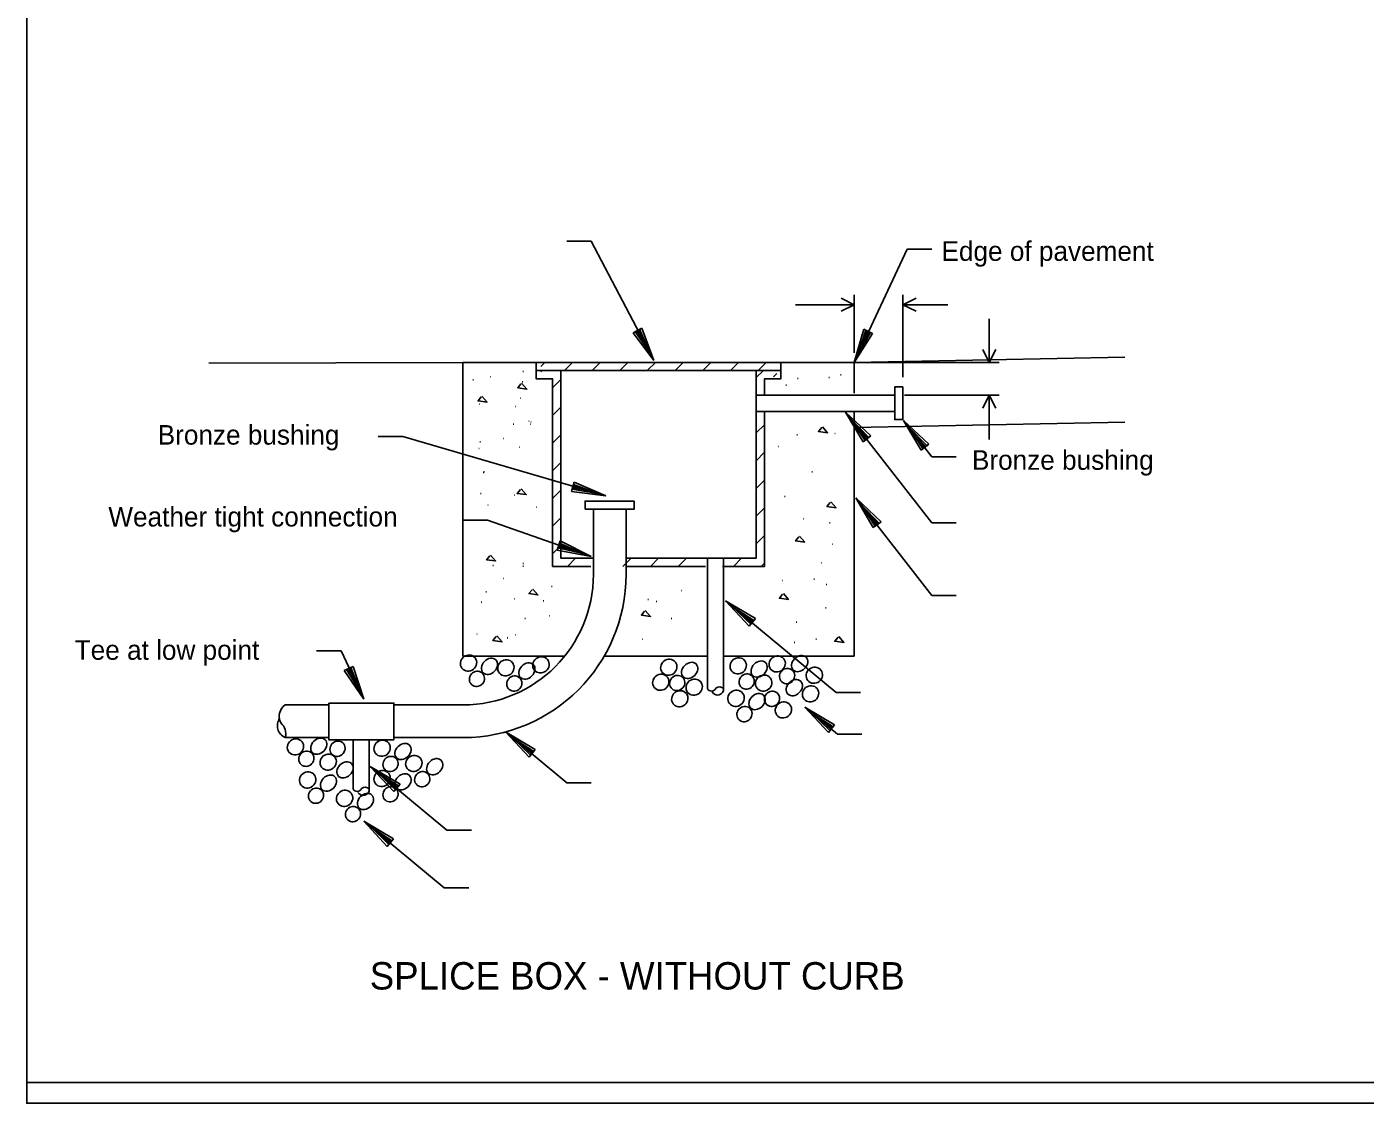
# Model space of a CAD drawing. Extents: x 0 to 390, y 0 to 265.
# Drawn here: x 0 to 160.8, y 0 to 129.2 of the extents above; entities that cross this region are included whole.
import ezdxf

# ---------------------------------------------------------------- set-up
doc = ezdxf.new("R2010")
doc.units = 0
doc.layers.add('D_Details', color=7, linetype='Continuous')
doc.layers.add('Default', color=7, linetype='Continuous')

msp = doc.modelspace()

# ---------------------------------------------------------------- linework, layer by layer
at = {"layer": 'D_Details'}
for p, q in [((67.82, 103.5), (64.88, 103.5)), ((67.82, 103.5), (75.32, 89.17)), ((105.78, 102.53), (99.39, 88.93)), ((105.78, 102.53), (108.72, 102.53)), ((99.39, 90.1), (99.39, 97.05)), ((105.26, 87.17), (105.26, 97.05)), ((99.39, 95.87), (92.34, 95.87)), ((105.26, 95.87), (110.64, 95.87)), ((115.62, 88.93), (115.62, 94.19)), ((73.88, 93.06), (72.84, 92.51)), ((72.84, 92.51), (75.32, 89.17)), ((74.85, 90.08), (73.1, 92.65)), ((74.07, 91.5), (73.23, 92.72)), ((73.5, 92.85), (74.07, 91.5)), ((73.63, 92.92), (74.85, 90.08)), ((75.32, 89.17), (73.88, 93.06)), ((100.55, 92.92), (99.39, 88.93)), ((99.39, 88.93), (101.61, 92.42)), ((99.82, 89.86), (100.82, 92.8)), ((101.35, 92.55), (99.82, 89.86)), ((100.48, 91.33), (100.95, 92.74)), ((101.22, 92.61), (100.48, 91.33)), ((101.61, 92.42), (100.55, 92.92)), ((52.4, 88.93), (21.87, 88.86)), ((52.4, 53.69), (52.4, 88.93)), ((52.4, 88.93), (59.8, 88.93)), ((59.8, 88.93), (99.39, 88.93)), ((61.19, 86.98), (61.19, 88.93)), ((61.75, 88.93), (61.19, 88.93)), ((61.75, 88.44), (62.24, 88.93)), ((61.75, 88.93), (89.47, 88.93)), ((89.47, 88.93), (61.75, 88.93)), ((89.47, 88.93), (91.63, 88.93)), ((99.39, 88.93), (131.92, 89.58)), ((99.39, 85.24), (99.39, 88.93)), ((99.39, 88.93), (102.32, 88.93)), ((100.56, 88.93), (116.8, 88.93)), ((53.59, 86.83), (53.65, 86.83)), ((55.7, 87.22), (55.75, 87.22)), ((59.61, 87.85), (59.67, 87.85)), ((61.75, 87.8), (61.92, 87.97)), ((61.75, 87.97), (89.47, 87.97)), ((87.64, 84.98), (87.64, 87.97)), ((88.63, 84.98), (88.63, 86.98)), ((89.47, 86.98), (88.63, 86.98)), ((90.6, 86.98), (89.47, 86.98)), ((89.71, 87.19), (90.11, 87.59)), ((90.6, 86.98), (90.6, 87.97)), ((92.61, 86.99), (92.67, 86.99)), ((96.36, 87.14), (96.42, 87.14)), ((97.77, 87.46), (97.83, 87.46)), ((59.53, 86.6), (59.59, 86.6)), ((91.2, 86.2), (91.26, 86.2)), ((54.37, 83.94), (54.43, 83.94)), ((58.67, 83.63), (58.73, 83.63)), ((59.3, 84.64), (59.35, 84.64)), ((87.64, 85.01), (104.27, 85.01)), ((87.64, 85.01), (87.64, 83.06)), ((105.45, 85.01), (116.8, 85.01)), ((115.62, 79.67), (115.62, 85.1)), ((87.64, 83.06), (104.27, 83.06)), ((87.64, 65.44), (87.64, 82.82)), ((88.63, 64.45), (88.63, 82.99)), ((108.72, 69.68), (98.37, 82.96)), ((98.37, 82.96), (100.48, 79.4)), ((101.41, 80.11), (98.37, 82.96)), ((98.37, 82.96), (100.48, 79.4)), ((101.41, 80.11), (98.37, 82.96)), ((100.71, 79.57), (99, 82.15)), ((99, 82.15), (101.18, 79.94)), ((100.71, 79.57), (99, 82.15)), ((99, 82.15), (101.18, 79.94)), ((99.39, 53.69), (99.39, 83.06)), ((58.44, 81.51), (58.5, 81.51)), ((60.31, 81.9), (60.37, 81.9)), ((60.47, 81.51), (60.53, 81.51)), ((60.55, 81.75), (60.61, 81.75)), ((97.07, 80.41), (97.12, 80.41)), ((99.39, 81.11), (131.92, 81.76)), ((100.82, 79.67), (100.02, 80.89)), ((100.02, 80.89), (101.06, 79.84)), ((100.82, 79.67), (100.02, 80.89)), ((100.02, 80.89), (101.06, 79.84)), ((108.72, 77.62), (105.32, 81.98)), ((105.32, 81.98), (107.43, 78.42)), ((108.35, 79.13), (105.32, 81.98)), ((107.66, 78.59), (105.95, 81.17)), ((105.95, 81.17), (108.12, 78.96)), ((42.23, 80.04), (45.16, 80.04)), ((45.16, 80.04), (69.57, 72.92)), ((54.44, 79.4), (54.5, 79.4)), ((57.26, 79.79), (57.32, 79.79)), ((90.26, 78.85), (90.32, 78.85)), ((92.53, 80.26), (92.58, 80.26)), ((100.48, 79.4), (101.41, 80.11)), ((100.48, 79.4), (101.41, 80.11)), ((107.77, 78.69), (106.97, 79.91)), ((106.97, 79.91), (108.01, 78.86)), ((107.43, 78.42), (108.35, 79.13)), ((54.29, 78.62), (54.34, 78.62)), ((59.14, 78.77), (59.2, 78.77)), ((108.72, 77.62), (111.65, 77.62)), ((54.84, 75.73), (54.9, 75.73)), ((54.91, 75.81), (54.97, 75.81)), ((94.33, 75.81), (94.39, 75.81)), ((65.77, 74.58), (65.44, 73.45)), ((65.64, 74.16), (67.02, 73.63)), ((65.69, 74.3), (68.58, 73.21)), ((69.57, 72.92), (65.77, 74.58)), ((54.52, 73.22), (54.58, 73.22)), ((58.59, 72.99), (58.65, 72.99)), ((65.44, 73.45), (69.57, 72.92)), ((68.58, 73.21), (65.52, 73.74)), ((67.02, 73.63), (65.56, 73.88)), ((91.04, 72.83), (91.1, 72.83)), ((108.72, 60.96), (99.59, 72.67)), ((99.59, 72.67), (101.7, 69.11)), ((102.63, 69.82), (99.59, 72.67)), ((55.38, 71.82), (55.44, 71.82)), ((61.18, 71.58), (61.23, 71.58)), ((68.07, 71.31), (71.99, 71.31)), ((68.07, 71.31), (68.07, 63.49)), ((71.99, 71.31), (71.99, 63.46)), ((101.93, 69.28), (100.23, 71.86)), ((100.23, 71.86), (102.4, 69.65)), ((52.42, 70.01), (55.35, 70.01)), ((55.35, 70.01), (67.79, 65.64)), ((93.31, 70.17), (93.37, 70.17)), ((96.44, 69.7), (96.5, 69.7)), ((102.05, 69.38), (101.24, 70.61)), ((101.24, 70.61), (102.28, 69.55)), ((101.7, 69.11), (102.63, 69.82)), ((108.72, 69.68), (111.65, 69.68)), ((64.09, 67.5), (63.7, 66.39)), ((63.7, 66.39), (67.79, 65.64)), ((66.82, 65.98), (63.8, 66.67)), ((65.29, 66.49), (63.85, 66.81)), ((63.94, 67.09), (65.29, 66.49)), ((63.99, 67.22), (66.82, 65.98)), ((67.79, 65.64), (64.09, 67.5)), ((96.75, 67.12), (96.81, 67.12)), ((56.01, 64.54), (56.07, 64.54)), ((59.61, 64.78), (59.67, 64.78)), ((59.61, 64.47), (59.67, 64.47)), ((81.77, 65.44), (81.77, 49.77)), ((83.72, 65.44), (83.72, 49.77)), ((95.42, 64.86), (95.48, 64.86)), ((57.26, 62.98), (57.32, 62.98)), ((90.73, 62.75), (90.79, 62.75)), ((94.56, 62.91), (94.62, 62.91)), ((55.15, 61.41), (55.21, 61.41)), ((63.04, 62.04), (63.1, 62.04)), ((78.61, 61.57), (78.67, 61.57)), ((96.05, 62.28), (96.11, 62.28)), ((54.6, 60.16), (54.66, 60.16)), ((58.59, 60.56), (58.65, 60.56)), ((62.04, 60.32), (62.1, 60.32)), ((74.62, 60.48), (74.68, 60.48)), ((75.63, 60.25), (75.69, 60.25)), ((97.23, 49.3), (83.96, 60.3)), ((83.96, 60.3), (86.79, 57.27)), ((87.54, 58.18), (83.96, 60.3)), ((86.98, 57.5), (84.76, 59.65)), ((84.76, 59.65), (87.35, 57.95)), ((108.72, 60.96), (111.65, 60.96)), ((59.84, 58.21), (59.9, 58.21)), ((62.74, 58.52), (62.8, 58.52)), ((77.43, 58.21), (77.49, 58.21)), ((87.07, 57.61), (86.02, 58.64)), ((86.02, 58.64), (87.26, 57.84)), ((86.79, 57.27), (87.54, 58.18)), ((95.97, 59.46), (96.03, 59.46)), ((54.05, 56.33), (54.11, 56.33)), ((92.45, 57.74), (92.51, 57.74)), ((57.73, 55.86), (57.79, 55.86)), ((58.67, 56.25), (58.73, 56.25)), ((73.92, 55.71), (73.98, 55.71)), ((92.21, 55.31), (92.27, 55.31)), ((94.8, 55.71), (94.86, 55.71)), ((34.81, 54.3), (37.75, 54.3)), ((37.75, 54.3), (40.49, 48.5)), ((52.4, 53.69), (64.5, 53.69)), ((69.34, 53.69), (81.65, 53.69)), ((83.83, 53.69), (99.39, 53.69)), ((39.21, 52.44), (38.15, 51.94)), ((38.15, 51.94), (40.49, 48.5)), ((40.05, 49.43), (38.41, 52.06)), ((39.33, 50.88), (38.55, 52.13)), ((38.81, 52.25), (39.33, 50.88)), ((38.95, 52.32), (40.05, 49.43)), ((40.49, 48.5), (39.21, 52.44)), ((97.23, 49.3), (100.17, 49.3)), ((36.28, 47.82), (31.05, 47.82)), ((52.4, 47.82), (44.11, 47.82)), ((97.4, 44.29), (93.47, 47.54)), ((93.47, 47.54), (96.3, 44.51)), ((97.05, 45.42), (93.47, 47.54)), ((96.49, 44.74), (94.26, 46.88)), ((94.26, 46.88), (96.86, 45.19)), ((96.58, 44.85), (95.53, 45.88)), ((95.53, 45.88), (96.77, 45.07)), ((96.3, 44.51), (97.05, 45.42)), ((36.28, 43.89), (31.05, 43.89)), ((39.2, 43.59), (39.2, 37.72)), ((41.15, 43.59), (41.15, 37.72)), ((52.42, 43.89), (44.11, 43.89)), ((64.88, 38.46), (57.51, 44.58)), ((57.51, 44.58), (60.34, 41.55)), ((61.09, 42.45), (57.51, 44.58)), ((60.52, 41.77), (58.3, 43.92)), ((58.3, 43.92), (60.9, 42.22)), ((97.4, 44.29), (100.34, 44.29)), ((60.62, 41.89), (59.57, 42.91)), ((59.57, 42.91), (60.81, 42.11)), ((60.34, 41.55), (61.09, 42.45)), ((50.48, 32.8), (41.27, 40.44)), ((41.27, 40.44), (44.09, 37.41)), ((44.84, 38.31), (41.27, 40.44)), ((41.27, 40.44), (44.09, 37.41)), ((44.84, 38.31), (41.27, 40.44)), ((44.28, 37.63), (42.06, 39.78)), ((42.06, 39.78), (44.65, 38.09)), ((44.28, 37.63), (42.06, 39.78)), ((42.06, 39.78), (44.65, 38.09)), ((44.37, 37.75), (43.32, 38.78)), ((43.32, 38.78), (44.56, 37.97)), ((44.37, 37.75), (43.32, 38.78)), ((43.32, 38.78), (44.56, 37.97)), ((44.09, 37.41), (44.84, 38.31)), ((44.09, 37.41), (44.84, 38.31)), ((64.88, 38.46), (67.82, 38.46)), ((50.15, 25.85), (40.48, 33.86)), ((40.48, 33.86), (43.31, 30.83)), ((44.06, 31.74), (40.48, 33.86)), ((40.48, 33.86), (43.31, 30.83)), ((44.06, 31.74), (40.48, 33.86)), ((43.5, 31.06), (41.28, 33.21)), ((41.28, 33.21), (43.87, 31.51)), ((43.5, 31.06), (41.28, 33.21)), ((41.28, 33.21), (43.87, 31.51)), ((43.59, 31.17), (42.54, 32.2)), ((42.54, 32.2), (43.78, 31.4)), ((43.59, 31.17), (42.54, 32.2)), ((42.54, 32.2), (43.78, 31.4)), ((50.48, 32.8), (53.42, 32.8)), ((43.31, 30.83), (44.06, 31.74)), ((43.31, 30.83), (44.06, 31.74)), ((50.15, 25.85), (53.09, 25.85))]:
    msp.add_line(p, q, dxfattribs=at)
for points in [[(97.82, 95.09), (99.39, 95.87), (97.82, 96.65)], [(106.83, 95.09), (105.26, 95.87), (106.83, 96.65)], [(114.84, 90.5), (115.62, 88.93), (116.41, 90.5)], [(61.19, 88.93), (61.19, 87.97), (61.75, 87.97)], [(64.59, 87.97), (65.56, 88.93)], [(67.93, 87.97), (68.89, 88.93)], [(71.24, 87.97), (72.2, 88.93)], [(74.55, 87.97), (75.52, 88.93)], [(77.89, 87.97), (78.85, 88.93)], [(81.2, 87.97), (82.17, 88.93)], [(84.54, 87.97), (85.5, 88.93)], [(87.85, 87.97), (88.81, 88.93)], [(89.47, 87.97), (90.6, 87.97), (90.6, 88.93), (89.47, 88.93)], [(61.75, 87.97), (61.19, 87.97), (61.19, 86.98), (61.75, 86.98)], [(68.09, 65.44), (64.15, 65.44), (64.15, 87.97), (61.75, 87.97)], [(61.75, 86.98), (63.16, 86.98), (63.16, 64.45), (67.76, 64.45)], [(63.16, 85.88), (64.15, 86.89)], [(87.64, 87.12), (88.51, 87.97)], [(89.47, 87.97), (87.64, 87.97), (87.64, 84.91)], [(88.63, 84.91), (88.63, 86.98), (89.47, 86.98)], [(89.47, 86.98), (90.6, 86.98), (90.6, 87.97), (89.47, 87.97)], [(59.37, 86.36), (58.98, 85.89), (60.08, 85.74), (59.45, 86.44)], [(54.6, 84.79), (54.21, 84.32), (55.3, 84.17), (54.68, 84.88)], [(114.84, 83.44), (115.62, 85.01), (116.41, 83.44)], [(63.16, 82.56), (64.15, 83.55)], [(87.64, 83.06), (87.64, 65.44), (71.95, 65.44)], [(83.58, 64.45), (88.63, 64.45), (88.63, 82.89)], [(87.64, 80.47), (88.63, 81.46)], [(95.5, 81.12), (95.11, 80.65), (96.2, 80.5), (95.58, 81.2)], [(63.16, 79.23), (64.15, 80.24)], [(87.64, 77.14), (88.63, 78.15)], [(63.16, 75.91), (64.17, 76.92)], [(87.64, 73.82), (88.63, 74.81)], [(59.3, 73.69), (58.91, 73.22), (60, 73.07), (59.38, 73.78)], [(63.16, 72.6), (64.15, 73.59)], [(87.64, 70.49), (88.63, 71.5)], [(96.52, 72.13), (96.13, 71.66), (97.22, 71.5), (96.6, 72.21)], [(63.16, 69.27), (64.15, 70.28)], [(87.62, 67.15), (88.63, 68.16)], [(92.76, 67.98), (92.37, 67.51), (93.47, 67.36), (92.84, 68.06)], [(63.16, 65.95), (64.15, 66.94)], [(55.62, 65.72), (55.23, 65.25), (56.32, 65.1), (55.7, 65.8)], [(64.97, 64.45), (65.98, 65.46)], [(71.62, 64.45), (72.63, 65.46)], [(71.95, 64.45), (81.55, 64.45)], [(74.95, 64.45), (75.94, 65.46)], [(78.27, 64.45), (79.28, 65.46)], [(84.91, 64.45), (85.9, 65.46)], [(88.23, 64.45), (88.63, 64.85)], [(60.71, 61.65), (60.32, 61.18), (61.41, 61.03), (60.79, 61.73)], [(90.8, 61.1), (90.42, 60.63), (91.51, 60.48), (90.89, 61.18)], [(74.23, 59.07), (73.84, 58.6), (74.94, 58.45), (74.31, 59.15)], [(56.4, 56.02), (56.01, 55.55), (57.1, 55.39), (56.48, 56.1)], [(97.46, 55.94), (97.07, 55.47), (98.16, 55.32), (97.54, 56.02)]]:
    msp.add_lwpolyline(points, dxfattribs=at)
for points in [[(105.26, 85.99), (105.26, 82.07), (104.27, 82.07), (104.27, 85.99)], [(67.08, 71.31), (72.96, 71.31), (72.96, 72.3), (67.08, 72.3)], [(36.28, 48.03), (36.28, 43.64), (44.11, 43.64), (44.11, 48.03)]]:
    msp.add_lwpolyline(points, close=True, dxfattribs=at)
for centre, radius, start, end in [((52.41, 63.48), 15.66, 270, 0), ((52.42, 63.48), 19.58, 270, 0), ((83.23, 49.31), 0.677, 43.105, 131.1702), ((82.26, 50.05), 0.565, 209.147, 336.179), ((82.99, 49.74), 0.731, 210.1653, 2.5068), ((32.01, 46.44), 1.69, 124.8676, 207.3006), ((31.63, 45.32), 1.53, 143.7751, 247.8097), ((29.48, 44.38), 1.64, 342.9718, 51.1262), ((39.7, 38), 0.565, 209.147, 336.179), ((40.42, 37.69), 0.731, 210.1653, 2.5068), ((40.66, 37.26), 0.677, 43.105, 131.1702)]:
    msp.add_arc(centre, radius, start, end, dxfattribs=at)
for centre, major_axis, ratio in [((53.07, 52.84), (-0.787, -0.623), 0.945815), ((55.59, 52.45), (-0.764, -0.775), 0.775089), ((57.56, 52.27), (-0.787, -0.623), 0.945815), ((61.77, 52.63), (-0.787, -0.623), 0.945815), ((77.13, 52.34), (-0.787, -0.623), 0.945815), ((85.47, 52.51), (-0.787, -0.623), 0.945815), ((87.98, 52.12), (-0.764, -0.775), 0.775089), ((90.15, 52.74), (-0.787, -0.623), 0.945815), ((92.85, 52.78), (-0.764, -0.775), 0.775089), ((54.08, 50.95), (-0.623, -0.705), 0.944876), ((60.08, 51.89), (-0.764, -0.775), 0.775089), ((76.17, 50.54), (-0.787, -0.623), 0.945815), ((78.14, 50.45), (-0.623, -0.705), 0.944876), ((79.64, 51.96), (-0.764, -0.775), 0.775089), ((86.48, 50.62), (-0.623, -0.705), 0.944876), ((88.52, 50.44), (-0.787, -0.623), 0.945815), ((91.34, 51.28), (-0.623, -0.705), 0.944876), ((94.61, 51.38), (-0.787, -0.623), 0.945815), ((58.57, 50.38), (-0.623, -0.705), 0.944876), ((80.18, 49.95), (-0.787, -0.623), 0.945815), ((92.21, 49.89), (-0.764, -0.775), 0.775089), ((94.16, 49.15), (-0.787, -0.623), 0.945815), ((78.45, 48.56), (-0.787, -0.623), 0.945815), ((85.21, 48.61), (-0.787, -0.623), 0.945815), ((87.73, 48.22), (-0.764, -0.775), 0.775089), ((89.53, 48.55), (-0.623, -0.705), 0.944876), ((90.9, 47.22), (-0.787, -0.623), 0.945815), ((86.22, 46.72), (-0.623, -0.705), 0.944876), ((32.28, 42.78), (-0.787, -0.623), 0.945815), ((35.08, 42.87), (-0.764, -0.775), 0.775089), ((37.33, 42.56), (-0.623, -0.705), 0.944876), ((42.69, 42.62), (-0.787, -0.623), 0.945815), ((33.58, 41.36), (-0.623, -0.705), 0.944876), ((36.21, 40.95), (-0.787, -0.623), 0.945815), ((45.2, 42.23), (-0.764, -0.775), 0.775089), ((46.5, 40.79), (-0.787, -0.623), 0.945815), ((38.23, 40.02), (-0.764, -0.775), 0.775089), ((43.7, 40.73), (-0.623, -0.705), 0.944876), ((49.01, 40.4), (-0.764, -0.775), 0.775089), ((33.74, 38.81), (-0.787, -0.623), 0.945815), ((36.25, 38.43), (-0.764, -0.775), 0.775089), ((42.69, 38.98), (-0.787, -0.623), 0.945815), ((45.2, 38.59), (-0.764, -0.775), 0.775089), ((47.51, 38.9), (-0.623, -0.705), 0.944876), ((34.75, 36.92), (-0.623, -0.705), 0.944876), ((38.18, 36.6), (-0.787, -0.623), 0.945815), ((40.69, 36.22), (-0.764, -0.775), 0.775089), ((43.7, 37.09), (-0.623, -0.705), 0.944876), ((39.19, 34.71), (-0.623, -0.705), 0.944876)]:
    msp.add_ellipse(centre, major_axis=major_axis, ratio=ratio, dxfattribs=at)
at = {"layer": 'Default'}
for points in [[(0, 265), (326.25, 265), (326.25, 255), (390, 255), (390, 37.5), (315, 37.5), (315, 0), (0, 0)], [(0, 262.5), (326.25, 262.5), (326.25, 252.5), (390, 252.5), (390, 40), (315, 40), (315, 2.5), (0, 2.5)]]:
    msp.add_lwpolyline(points, close=True, dxfattribs=at)

# ---------------------------------------------------------------- texts
at = {"layer": 'D_Details'}
for s, height, p in [('Edge of pavement', 2.3493, (109.89, 101.13)), ('Bronze bushing', 2.3493, (15.73, 79.07)), ('Bronze bushing', 2.3493, (113.55, 76.05)), ('Weather tight connection', 2.3493, (9.8, 69.24)), ('Tee at low point', 2.3493, (5.76, 53.24)), ('SPLICE BOX - WITHOUT CURB', 3.2889, (41.2, 13.65))]:
    msp.add_text(s, height=height, dxfattribs=at).set_placement(p)

doc.saveas('drawing.dxf')
